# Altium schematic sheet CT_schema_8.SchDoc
size 384 x 301 mm
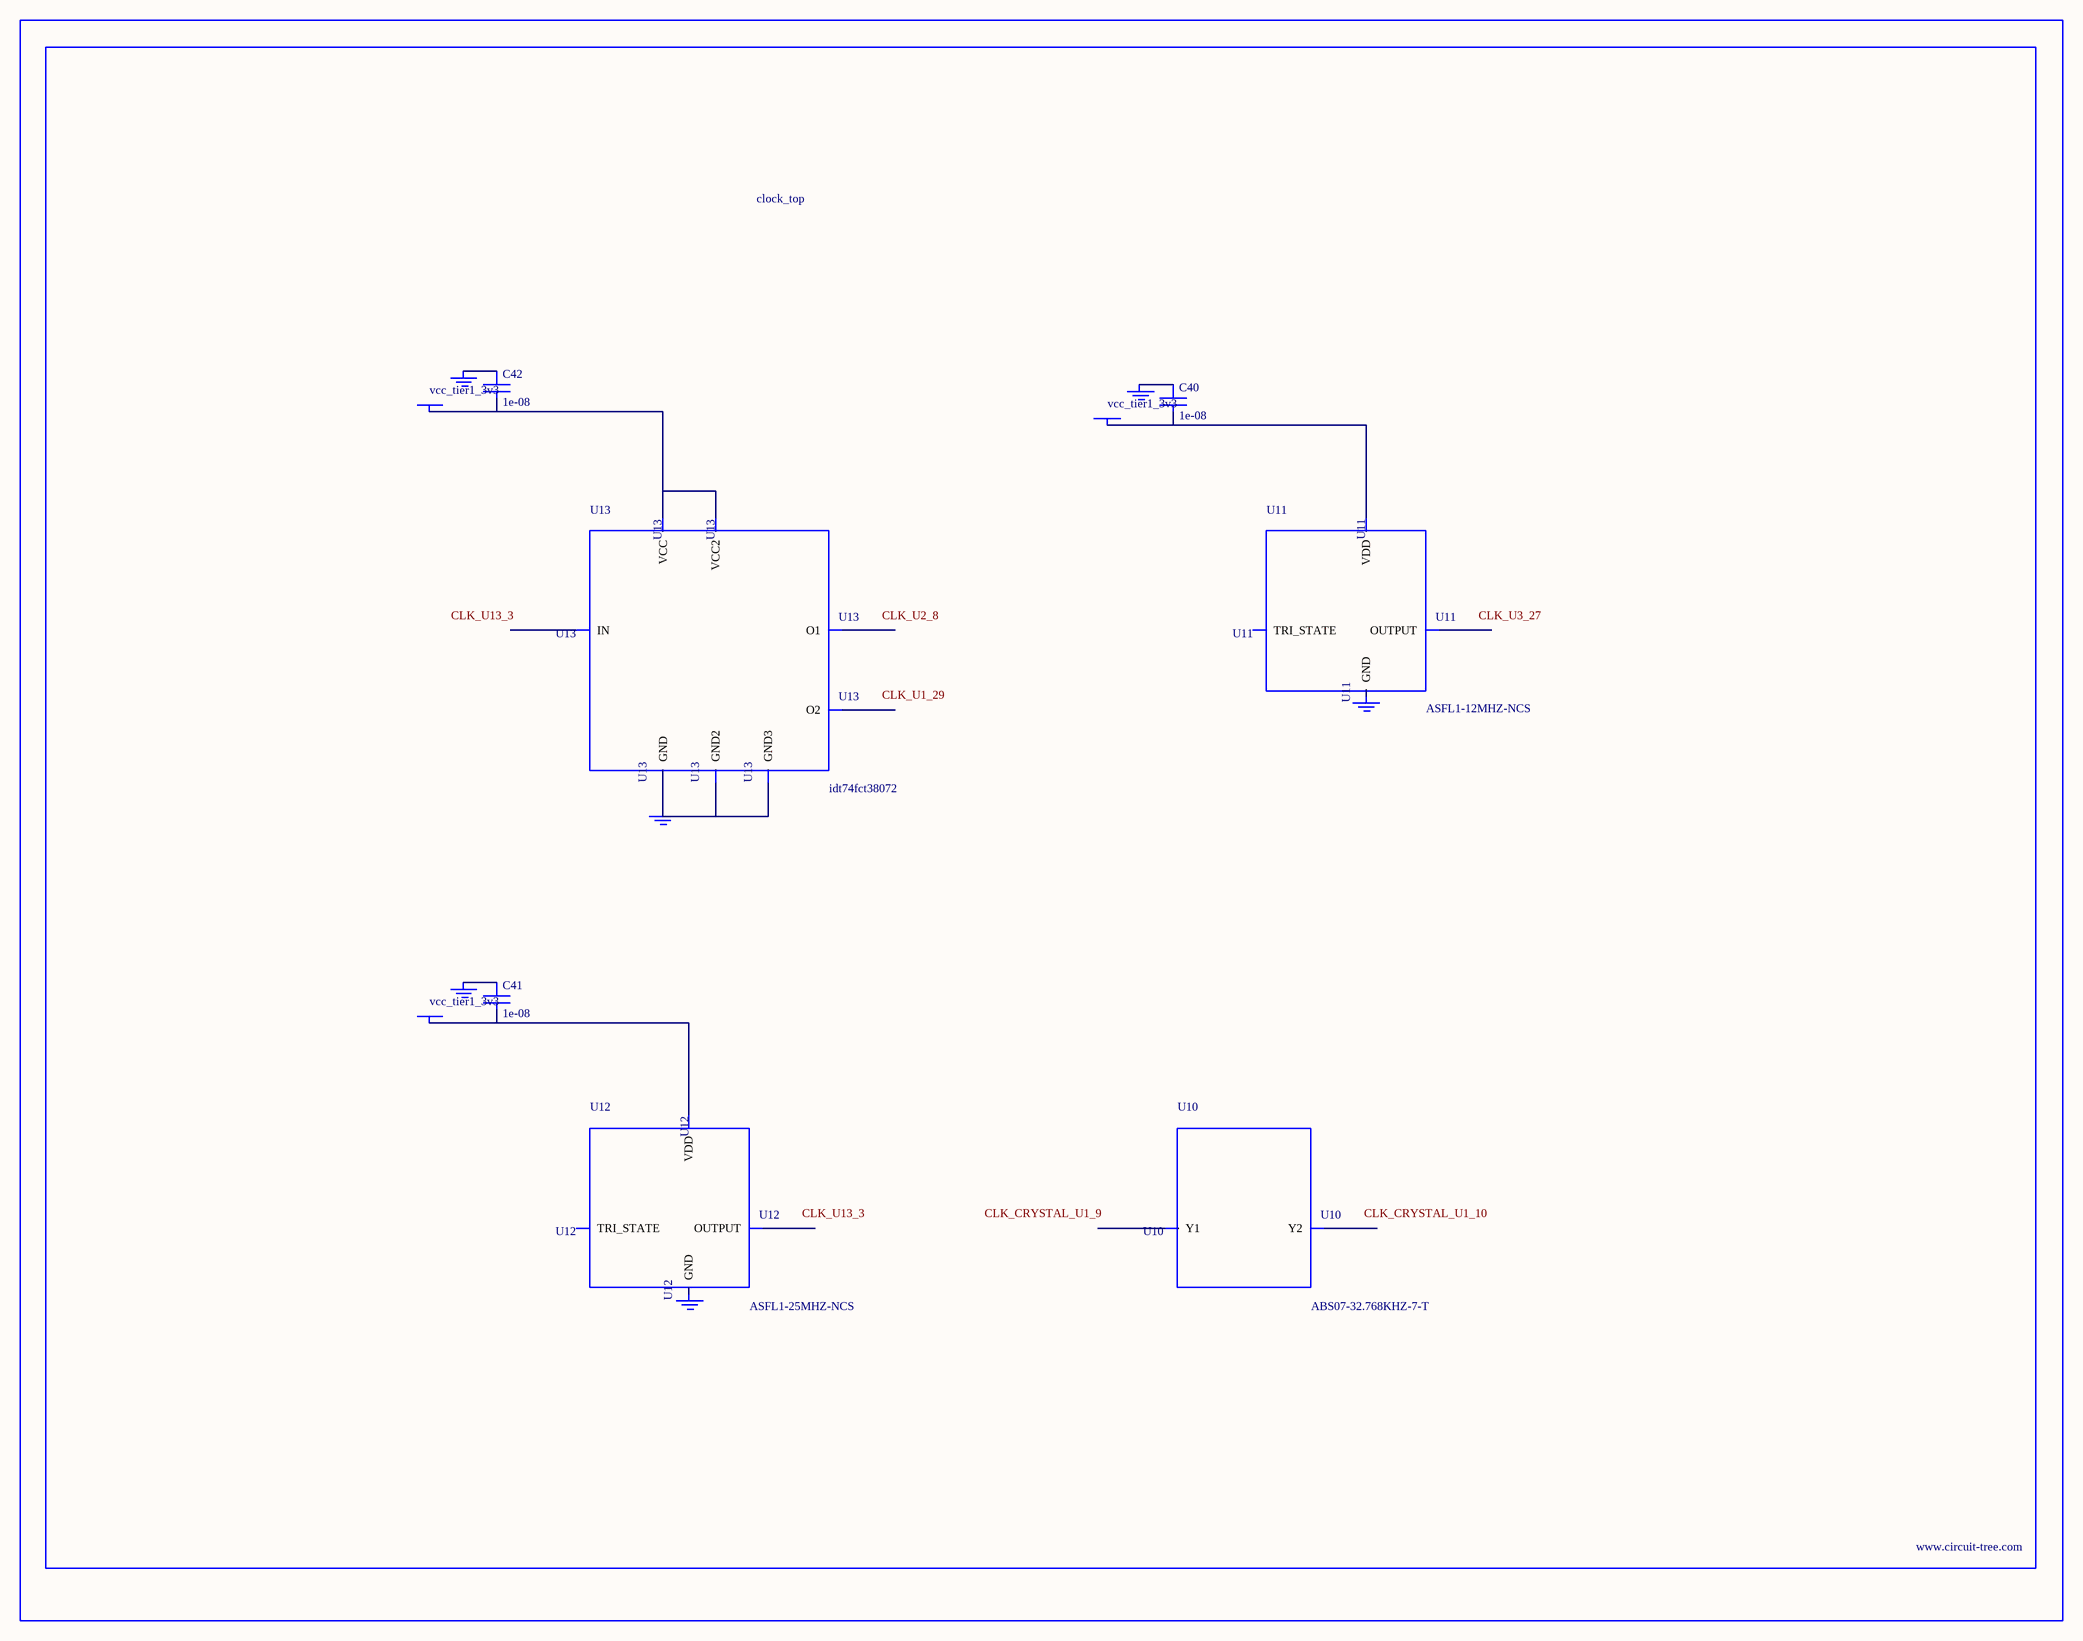
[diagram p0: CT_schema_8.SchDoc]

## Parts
BORDER7  (no value)
C40  1e-08  [C0402]
C41  1e-08  [C0402]
C42  1e-08  [C0402]
GND_INSTANCE_7_0  (no value)
GND_INSTANCE_7_1  (no value)
GND_INSTANCE_7_2  (no value)
GND_INSTANCE_7_3  (no value)
GND_INSTANCE_7_4  (no value)
GND_INSTANCE_7_5  (no value)
POWER_INSTANCE_7_0  vcc_tier1_3v3
POWER_INSTANCE_7_1  vcc_tier1_3v3
POWER_INSTANCE_7_2  vcc_tier1_3v3
U10  ABS07-32.768KHZ-7-T  [ABS07-32.768KHZ-7-T]
U11  ASFL1-12MHZ-NCS  [ASFL1]
U12  ASFL1-25MHZ-NCS  [ASFL1]
U13  idt74fct38072  [IDT74FCT38072]

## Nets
NetC40_1: C40.1 GND_INSTANCE_7_0.0(GND)
NetC40_2: C40.2 POWER_INSTANCE_7_0.0(PWR) U11.4(VDD)
NetC41_1: C41.1 GND_INSTANCE_7_2.0(GND)
NetC41_2: C41.2 POWER_INSTANCE_7_1.0(PWR) U12.4(VDD)
NetC42_1: C42.1 GND_INSTANCE_7_4.0(GND)
NetC42_2: C42.2 POWER_INSTANCE_7_2.0(PWR) U13.1(VCC) U13.2(VCC2)
NetGND_INSTANCE_7_5_0: GND_INSTANCE_7_5.0(GND) U13.4(GND) U13.5(GND2) U13.8(GND3)

Not connected (* = marked no-connect by the designer): GND_INSTANCE_7_1 0(GND); GND_INSTANCE_7_3 0(GND); U10 1(Y1) 2(Y2); U11 1(TRI_STATE) 2(GND) 3(OUTPUT); U12 1(TRI_STATE) 2(GND) 3(OUTPUT); U13 3(IN) 6(O2) 7(O1)

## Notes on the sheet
- Labels drawn without touching a wire or pin: CLK_CRYSTAL_U1_9, CLK_CRYSTAL_U1_10, CLK_U1_29, CLK_U2_8, CLK_U3_27, CLK_U13_3

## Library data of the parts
BORDER7 = BORDER_PAGE7
C40-C42 = C0402C103K3RAC
GND_INSTANCE_7_0-GND_INSTANCE_7_5 = GND
POWER_INSTANCE_7_0-POWER_INSTANCE_7_2 = PWR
